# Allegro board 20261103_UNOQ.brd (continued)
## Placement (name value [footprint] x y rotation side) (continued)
NOREF#421  -  []  31.09 37.5 90 top
NOREF#422  -  []  26.18 34.44 90 top
NOREF#423  -  []  37.33 23.09 0 top
NOREF#424  -  []  32.63 31.65 0 top
NOREF#425  -  []  29.98 33.33 0 top
NOREF#426  -  []  11.96 5.57 0 top
NOREF#427  -  []  45.29 17.84 90 top
NOREF#428  -  []  38.04 5.75 90 top
NOREF#429  -  []  30.29 30.35 0 top
NOREF#430  -  []  25.17 14.33 90 top
NOREF#431  -  []  27.21 32.29 90 top
NOREF#432  -  []  39.59 23.12 0 top
NOREF#433  -  []  44.99 18.44 0 top
NOREF#434  -  []  6.83 30.58 0 top
NOREF#435  -  []  34.16 18.53 0 top
NOREF#436  -  []  38.35 10.47 90 top
NOREF#437  -  []  39.39 14.38 90 top
NOREF#438  -  []  51.05 59.19 0 top
NOREF#439  -  []  41.22 9.92 90 top
NOREF#440  -  []  4.79 58.74 0 top
NOREF#441  -  []  5.44 49.74 0 top
NOREF#442  -  [unnamed#2]  44.5 66.45 0 top
NOREF#443  -  []  34.13 49.99 0 top
NOREF#444  -  []  29.47 31.59 0 top
NOREF#445  -  []  33.69 37.47 90 top
NOREF#446  -  []  41.26 22.12 0 top
NOREF#447  -  []  22.48 4.07 90 top
NOREF#448  -  []  41.81 20.07 0 top
NOREF#449  -  []  37.38 20.26 0 top
NOREF#450  -  []  7.05 6.87 0 top
NOREF#451  -  []  34.08 34.26 90 top
NOREF#452  -  []  43.1 31.9 90 top
NOREF#453  -  []  22.61 16.36 90 top
NOREF#454  -  []  7.18 25.96 90 top
NOREF#455  -  []  16.45 23.37 0 top
NOREF#456  -  []  35.54 51.37 90 top
NOREF#457  -  []  30.81 29.87 90 top
NOREF#458  -  []  40.64 10.86 90 top
NOREF#459  -  []  36.64 51.25 0 top
NOREF#460  -  []  8.61 28.94 90 top
NOREF#461  -  []  33.21 30.88 0 top
NOREF#462  -  []  46.19 16.1 90 top
NOREF#463  -  []  7.42 30.66 0 top
NOREF#464  -  []  28.23 32.6 0 top
NOREF#465  -  []  31.5 29.7 0 top
NOREF#466  -  []  34.01 9.61 90 top
NOREF#467  -  []  14.91 52.28 90 top
NOREF#468  -  []  31.71 34.63 0 top
NOREF#469  -  []  28.69 12.65 90 top
NOREF#470  -  []  37.3 10.44 90 top
NOREF#471  -  []  26.86 31.75 90 top
NOREF#472  -  []  23.52 13.83 90 top
NOREF#473  -  []  35.32 55.63 0 top
NOREF#474  -  []  33.53 61.86 0 top
NOREF#475  -  []  21.25 3.91 0 top
NOREF#476  -  []  8.06 50.09 90 top
NOREF#477  -  []  9.5 38.04 90 top
NOREF#478  -  []  28.64 34.69 0 top
NOREF#479  -  []  50.8 22.86 90 top
NOREF#480  -  []  43.57 4.06 0 top
NOREF#481  -  []  21.53 14.32 0 top
NOREF#482  -  []  43.21 13.46 90 top
NOREF#483  -  []  41.45 32 0 top
NOREF#484  -  []  43.21 21.14 90 top
NOREF#485  -  []  33.31 34.78 0 top
NOREF#486  -  []  29.04 34.07 0 top
NOREF#487  -  []  13.14 34.87 90 top
NOREF#488  -  []  39.4 10.49 90 top
NOREF#489  -  []  12.45 0.62 90 top
NOREF#490  -  []  9.11 18.79 0 top
NOREF#491  -  []  40.45 33.9 0 top
NOREF#492  -  []  28.13 19.88 0 top
NOREF#493  -  []  30.46 37.19 90 top
NOREF#494  -  []  41.87 62.36 0 top
NOREF#495  -  []  33.1 31.5 0 top
NOREF#496  -  []  30.76 64.3 0 top
NOREF#497  -  []  28.33 63.1 90 top
NOREF#498  -  []  42.31 58.24 0 top
NOREF#499  -  []  36.7 52.56 90 top
NOREF#500  -  []  4.5 60.95 0 top
NOREF#501  -  []  23.52 13.83 0 top
NOREF#502  -  []  33.34 44.07 0 top
NOREF#503  -  []  29.65 29.62 0 top
NOREF#504  -  []  45.77 18.19 0 top
NOREF#505  -  []  29.05 35.73 90 top
NOREF#506  -  []  34.78 58.56 0 top
NOREF#507  -  []  6.21 49.48 0 top
NOREF#508  -  []  42.63 15.87 0 top
NOREF#509  -  []  29.7 33.01 90 top
NOREF#510  -  []  41.81 10.61 0 top
NOREF#511  -  []  28.91 63.42 90 top
NOREF#512  -  [unnamed#2]  50.8 53.34 0 top
NOREF#513  -  []  7.77 26.77 0 top
NOREF#514  -  []  29.85 17.44 0 top
NOREF#515  -  []  43.44 18.19 0 top
NOREF#516  -  []  30.5 38.22 0 top
NOREF#517  -  []  14.76 28.44 90 top
NOREF#518  -  []  6.37 57.11 0 top
NOREF#519  -  []  37.81 11.06 0 top
NOREF#520  -  []  6.47 25.38 0 top
NOREF#521  -  []  30.67 62.44 90 top
NOREF#522  -  []  37.06 49.13 90 top
NOREF#523  -  []  7.65 19.81 0 top
NOREF#524  -  []  30.01 30.78 90 top
NOREF#525  -  []  30.81 30.47 0 top
NOREF#526  -  []  33.22 53.5 90 top
NOREF#527  -  []  33.32 35.31 0 top
NOREF#528  -  []  43.77 16.91 0 top
NOREF#529  -  []  44.22 15.71 90 top
NOREF#530  -  []  38.72 27.21 90 top
NOREF#531  -  []  16.85 14.12 0 top
NOREF#532  -  []  43.72 4.91 0 top
NOREF#533  -  []  31.05 30.77 90 top
NOREF#534  -  []  26.11 13.85 90 top
NOREF#535  -  []  44.73 30.54 0 top
NOREF#536  -  []  44.53 45.74 90 top
NOREF#537  -  []  29.36 30.93 90 top
NOREF#538  -  []  13.92 20.21 0 top
NOREF#539  -  []  48.83 4.06 90 top
NOREF#540  -  []  39.4 12.15 0 top
NOREF#541  -  []  35.42 13.84 0 top
NOREF#542  -  []  31.55 36.55 0 top
NOREF#543  -  []  22.69 39.25 0 top
NOREF#544  -  []  29.37 36.58 0 top
NOREF#545  -  []  40.31 8.78 90 top
NOREF#546  -  []  16.38 49.79 90 top
NOREF#547  -  []  7.6 54.01 0 top
NOREF#548  -  []  9.19 19.77 90 top
NOREF#549  -  []  10.25 60.8 0 top
NOREF#550  -  []  29.05 37.29 90 top
NOREF#551  -  []  44.64 58.5 90 top
NOREF#552  -  []  25.55 61.39 0 top
NOREF#553  -  []  18.82 32.36 0 top
NOREF#554  -  []  25.91 35.59 0 top
NOREF#555  -  []  22.72 24.8 90 top
NOREF#556  -  []  21 13.82 90 top
NOREF#557  -  []  33.58 19.76 0 top
NOREF#558  -  []  12.09 39.74 90 top
NOREF#559  -  []  25.14 33.68 0 top
NOREF#560  -  []  22.6 4.75 90 top
NOREF#561  -  []  14.3 6.28 90 top
NOREF#562  -  []  29.46 64.99 90 top
NOREF#563  -  []  32.07 35.37 90 top
NOREF#564  -  []  31.07 32.41 90 top
NOREF#565  -  []  9.19 20.37 0 top
NOREF#566  -  []  12.09 31.7 0 top
NOREF#567  -  []  40.64 11.38 90 top
NOREF#568  -  []  27.86 29.22 0 top
NOREF#569  -  []  22.36 5.02 90 top
NOREF#570  -  []  15.78 49.79 0 top
NOREF#571  -  []  20.22 6.33 0 top
NOREF#572  -  []  31.19 16.1 0 top
NOREF#573  -  []  13.02 53.22 90 top
NOREF#574  -  []  42.85 58.66 90 top
NOREF#575  -  []  27.3 13.38 90 top
NOREF#576  -  []  38.62 59.48 0 top
NOREF#577  -  []  33.42 29.65 90 top
NOREF#578  -  []  37 46.32 90 top
NOREF#579  -  []  30.74 33.85 90 top
NOREF#580  -  []  34.25 24.2 90 top
NOREF#581  -  []  22.25 28.65 0 top
NOREF#582  -  []  15.57 14.13 0 top
NOREF#583  -  []  23.47 55.71 90 top
NOREF#584  -  []  43.3 62.26 0 top
NOREF#585  -  []  11.38 50.09 90 top
NOREF#586  -  []  32.38 36.21 90 top
NOREF#587  -  []  25.91 36.13 0 top
NOREF#588  -  []  4.79 44.83 0 top
NOREF#589  -  []  38.28 22.04 0 top
NOREF#590  -  []  32.03 31.65 90 top
NOREF#591  -  []  7.16 19.18 90 top
NOREF#592  -  []  34.1 33.7 90 top
NOREF#593  -  []  17.56 45.35 90 top
NOREF#594  -  []  39.4 11.55 90 top
NOREF#595  -  []  39.75 32.83 0 top
NOREF#596  -  []  12.05 59.96 0 top
NOREF#597  -  []  15.85 52.5 90 top
NOREF#598  -  []  7.02 6.4 90 top
NOREF#599  -  []  40 33.25 90 top
NOREF#600  -  []  32.79 29.83 90 top
NOREF#601  -  []  33.1 49.59 90 top
NOREF#602  -  []  43.18 28.15 0 top
NOREF#603  -  []  33.89 45.89 90 top
NOREF#604  -  []  37.38 56.28 90 top
NOREF#605  -  []  46.8 58.49 0 top
NOREF#606  -  []  17.34 41.32 90 top
NOREF#607  -  []  7.29 21.97 0 top
NOREF#608  -  []  15.95 25.93 90 top
NOREF#609  -  []  17.61 13.49 90 top
NOREF#610  -  []  28.45 36.24 0 top
NOREF#611  -  []  39.75 34.98 90 top
NOREF#612  -  []  22.61 15.8 90 top
NOREF#613  -  []  21.67 40.32 0 top
NOREF#614  -  []  34.42 61.21 90 top
NOREF#615  -  []  20.99 4.75 90 top
NOREF#616  -  []  14.19 7.13 0 top
NOREF#617  -  []  22.99 38.11 90 top
NOREF#618  -  []  40.55 39.2 0 top
NOREF#619  -  []  8.44 13.65 0 top
NOREF#620  -  []  32.39 14.3 90 top
NOREF#621  -  []  32.8 18.91 0 top
NOREF#622  -  []  6.38 43.29 90 top
NOREF#623  -  []  14.99 37.82 90 top
NOREF#624  -  []  46.31 5.84 0 top
NOREF#625  -  []  35.74 11.53 90 top
NOREF#626  -  []  35.45 26.85 0 top
NOREF#627  -  []  11.48 31.49 0 top
NOREF#628  -  []  33.66 32.42 90 top
NOREF#629  -  []  13.03 13.63 90 top
NOREF#630  -  []  27.01 29.28 0 top
NOREF#631  -  []  11.2 14.13 90 top
NOREF#632  -  []  28.66 62.62 0 top
NOREF#633  -  []  28.29 38.06 90 top
NOREF#634  -  []  36.25 9.99 0 top
NOREF#635  -  []  32.67 35.37 0 top
NOREF#636  -  []  14.96 31.45 0 top
NOREF#637  -  []  40.19 12.4 0 top
NOREF#638  -  []  35.77 40.48 90 top
NOREF#639  -  []  25.31 35.59 90 top
NOREF#640  -  []  17.05 23.97 90 top
NOREF#641  -  []  28.63 37.64 0 top
NOREF#642  -  []  36.8 56.29 90 top
NOREF#643  -  []  30.07 31.59 90 top
NOREF#644  -  []  24.72 38.48 90 top
NOREF#645  -  []  33.68 13.24 90 top
NOREF#646  -  []  42.17 59.02 0 top
NOREF#647  -  []  19.05 49.79 0 top
NOREF#648  -  []  12.17 36.63 90 top
NOREF#649  -  []  46.23 47.26 0 top
NOREF#650  -  []  9.18 33.48 90 top
NOREF#651  -  []  34.25 25.25 90 top
NOREF#652  -  []  37.84 17.12 90 top
NOREF#653  -  []  15.9 37.12 90 top
NOREF#654  -  []  10.21 19.77 90 top
NOREF#655  -  []  13.94 18.24 90 top
NOREF#656  -  []  45.24 58.5 0 top
NOREF#657  -  []  39.11 53.14 90 top
NOREF#658  -  []  11.61 16.59 90 top
NOREF#659  -  []  38.71 43.35 0 top
NOREF#660  -  []  28.86 62.38 90 top
NOREF#661  -  []  35.57 37.88 90 top
NOREF#662  -  []  47.5 66.64 0 top
NOREF#663  -  []  9.51 19.01 90 top
NOREF#664  -  []  10.74 19.77 90 top
NOREF#665  -  []  38.81 53.74 0 top
NOREF#666  -  []  43.49 42.74 90 top
NOREF#667  -  []  42.35 30.8 90 top
NOREF#668  -  []  13.28 53.24 90 top
NOREF#669  -  []  26.15 38.35 90 top
NOREF#670  -  []  23.02 57.58 0 top
NOREF#671  -  []  35.06 51.14 90 top
NOREF#672  -  []  36.8 55.69 0 top
NOREF#673  -  []  25.25 59.23 90 top
NOREF#674  -  []  42.62 42.74 90 top
NOREF#675  -  []  44.21 23.17 0 top
NOREF#676  -  []  7.5 27.91 90 top
NOREF#677  -  []  13.28 53.27 0 top
NOREF#678  -  []  14.3 14.13 0 top
NOREF#679  -  []  30.61 30.78 0 top
NOREF#680  -  []  14.45 59.96 0 top
NOREF#681  -  []  33 34.44 90 top
NOREF#682  -  []  19.33 6.62 0 top
NOREF#683  -  []  29.89 12.8 0 top
NOREF#684  -  []  32.63 36.81 0 top
NOREF#685  -  []  36.25 12.13 0 top
NOREF#686  -  []  31.2 35.75 90 top
NOREF#687  -  []  42.05 33.1 0 top
NOREF#688  -  []  42.63 16.39 0 top
NOREF#689  -  []  36.77 9.99 0 top
NOREF#690  -  []  7.72 30.06 90 top
NOREF#691  -  []  28.91 63.91 0 top
NOREF#692  -  []  26.87 32.97 90 top
NOREF#693  -  []  30.5 37.62 90 top
NOREF#694  -  []  37.72 57.46 90 top
NOREF#695  -  []  39.14 50.07 90 top
NOREF#696  -  []  11.85 13.52 0 top
NOREF#697  -  []  30.56 15.71 0 top
NOREF#698  -  []  7.13 24.67 90 top
NOREF#699  -  []  13.18 40.05 0 top
NOREF#700  -  []  46.36 32 0 top
NOREF#701  -  []  14.96 32.05 90 top
NOREF#702  -  []  43.4 48.14 0 top
NOREF#703  -  []  34.45 14.28 90 top
NOREF#704  -  []  36.7 43.04 90 top
NOREF#705  -  []  34.45 18.81 0 top
NOREF#706  -  []  17.85 31.66 0 top
NOREF#707  -  []  25.73 13.58 0 top
NOREF#708  -  []  31.47 61.95 90 top
NOREF#709  -  []  22.69 39.76 0 top
NOREF#710  -  []  31.34 33.85 0 top
NOREF#711  -  []  27.78 34.51 90 top
NOREF#712  -  []  32.19 30.85 0 top
NOREF#713  -  []  22.88 14.23 90 top
NOREF#714  -  []  38.12 27.51 0 top
NOREF#715  -  []  20.22 15.05 90 top
NOREF#716  -  []  9.18 35.08 0 top
NOREF#717  -  []  16.26 22.23 0 top
NOREF#718  -  []  32.77 10.29 90 top
NOREF#719  -  []  42.38 58.95 90 top
NOREF#720  -  []  30.67 18.33 90 top
NOREF#721  -  []  31.75 35.16 0 top
NOREF#722  -  []  24.49 13.62 90 top
NOREF#723  -  []  46.33 32.64 90 top
NOREF#724  -  []  14.99 37.22 0 top
NOREF#725  -  []  49.55 3.56 0 top
NOREF#726  -  []  40.04 11.38 0 top
NOREF#727  -  []  32.44 43.47 90 top
NOREF#728  -  []  8.12 38.81 0 top
NOREF#729  -  []  44.66 57.55 0 top
NOREF#730  -  []  43.21 14.06 0 top
NOREF#731  -  []  29.14 38.23 90 top
NOREF#732  -  []  43.5 24.23 0 top
NOREF#733  -  []  36.99 43.47 0 top
NOREF#734  -  []  40.43 5.34 90 top
NOREF#735  -  []  44.66 57.55 90 top
NOREF#736  -  []  22.2 13.59 90 top
NOREF#737  -  []  26.36 32.97 90 top
NOREF#738  -  []  8.5 43.1 0 top
NOREF#739  -  []  20.34 4.01 90 top
NOREF#740  -  []  32.39 13.28 90 top
NOREF#741  -  []  42.63 16.92 0 top
NOREF#742  -  []  39.11 52.63 90 top
NOREF#743  -  []  46.26 40.46 90 top
NOREF#744  -  []  31.77 50.66 90 top
NOREF#745  -  []  34.03 23.1 0 top
NOREF#746  -  []  1.06 49.93 0 top
NOREF#747  -  []  27.29 13.41 90 top
NOREF#748  -  []  30.62 22.07 90 top
NOREF#749  -  []  29.36 30.33 0 top
NOREF#750  -  []  36.78 10.44 90 top
NOREF#751  -  []  28.03 63.19 0 top
NOREF#752  -  []  15.98 27.43 90 top
NOREF#753  -  []  36.39 58.05 90 top
NOREF#754  -  []  39.4 43.42 0 top
NOREF#755  -  []  45.12 21.66 0 top
NOREF#756  -  []  10.9 31.85 90 top
NOREF#757  -  []  40 29.9 90 top
NOREF#758  -  []  37.71 39.22 0 top
NOREF#759  -  []  32.57 49.59 90 top
NOREF#760  -  []  13.36 16.12 0 top
NOREF#761  -  []  45.02 4.06 90 top
NOREF#762  -  []  42.17 61.86 90 top
NOREF#763  -  []  32.64 32.67 0 top
NOREF#764  -  []  46.17 12.58 0 top
NOREF#765  -  []  21.97 38.65 90 top
NOREF#766  -  []  29.05 36.24 90 top
NOREF#767  -  []  15.22 42.62 0 top
NOREF#768  -  []  7.6 52.87 90 top
NOREF#769  -  []  14.65 53.7 0 top
NOREF#770  -  []  43.62 4.01 0 top
NOREF#771  -  []  16.22 36.1 90 top
NOREF#772  -  []  30.12 19.23 90 top
NOREF#773  -  []  15.45 49.58 90 top
NOREF#774  -  []  44.17 4.91 0 top
NOREF#775  -  []  38.22 21.23 90 top
NOREF#776  -  []  21.16 6.29 90 top
NOREF#777  -  []  30.6 35.75 0 top
NOREF#778  -  []  47.38 4.06 0 top
NOREF#779  -  []  17.85 33.87 0 top
NOREF#780  -  []  20.86 15.24 0 top
NOREF#781  -  []  36.76 49.73 0 top
NOREF#782  -  []  22.85 28.65 0 top
NOREF#783  -  []  31.53 38.71 90 top
NOREF#784  -  []  27.85 30.1 0 top
NOREF#785  -  []  32.79 9.55 90 top
NOREF#786  -  []  14.14 52.54 90 top
NOREF#787  -  []  44.59 42.55 90 top
NOREF#788  -  []  43.05 42.77 90 top
NOREF#789  -  []  15.97 20.4 0 top
NOREF#790  -  []  36.45 13.84 0 top
NOREF#791  -  []  18.58 36.25 90 top
NOREF#792  -  []  12.79 53.02 90 top
NOREF#793  -  []  7.87 21.37 90 top
NOREF#794  -  []  29.1 19.23 90 top
NOREF#795  -  []  26.77 36.61 0 top
NOREF#796  -  []  26.2 31.04 0 top
NOREF#797  -  []  35.08 57.97 90 top
NOREF#798  -  []  29.12 30.86 0 top
NOREF#799  -  []  46.47 3.06 90 top
NOREF#800  -  []  45.47 4.06 0 top
NOREF#801  -  []  39.97 27.68 0 top
NOREF#802  -  []  17.17 13.5 90 top
NOREF#803  -  []  30.74 33.34 90 top
NOREF#804  -  []  14.64 32.39 90 top
NOREF#805  -  []  44.21 21.14 0 top
NOREF#806  -  []  7.1 4.77 0 top
NOREF#807  -  [unnamed#2]  2.54 54.61 0 top
NOREF#808  -  []  8.9 21.61 90 top
NOREF#809  -  []  39.1 34.95 90 top
NOREF#810  -  []  8.84 29.54 0 top
NOREF#811  -  []  34.97 61.23 0 top
NOREF#812  -  []  28.5 59.57 90 top
NOREF#813  -  []  34.54 34.83 90 top
NOREF#814  -  []  18.46 5.95 0 top
NOREF#815  -  []  28.87 63.91 0 top
NOREF#816  -  []  38.43 5.78 0 top
NOREF#817  -  []  25.73 34.57 0 top
NOREF#818  -  []  45.26 18.38 90 top
NOREF#819  -  []  28.45 35.73 0 top
NOREF#820  -  []  12.13 31.77 90 top
NOREF#821  -  []  35.7 52.45 0 top
NOREF#822  -  []  29.28 35.21 90 top
NOREF#823  -  []  24.85 58.48 90 top
NOREF#824  -  []  45.62 4.91 0 top
NOREF#825  -  []  17.73 64.55 0 top
NOREF#826  -  []  37.3 11.04 0 top
NOREF#827  -  []  30.99 37.19 90 top
NOREF#828  -  []  19.63 32.62 0 top
NOREF#829  -  []  6.96 37.6 90 top
NOREF#830  -  []  30.26 61.59 0 top
NOREF#831  -  []  11.85 14.12 90 top
NOREF#832  -  []  12.68 40.05 0 top
NOREF#833  -  []  13.03 14.13 0 top
NOREF#834  -  []  30.38 32 90 top
NOREF#835  -  []  29.14 33.01 90 top
NOREF#836  -  []  11.87 20.6 0 top
NOREF#837  -  []  45.62 45.85 90 top
NOREF#838  -  []  36.37 49.13 90 top
NOREF#839  -  []  29.19 63.29 90 top
NOREF#840  -  []  30.37 63.04 0 top
NOREF#841  -  []  28.45 57.12 0 top
NOREF#842  -  []  14.46 29.64 0 top
NOREF#843  -  []  35.86 49.13 90 top
NOREF#844  -  []  39 55.87 0 top
NOREF#845  -  []  44.38 42.74 90 top
NOREF#846  -  []  34.03 23.73 0 top
NOREF#847  -  []  15.57 13.63 90 top
NOREF#848  -  []  33.68 49.91 0 top
NOREF#849  -  []  35.14 15.92 0 top
NOREF#850  -  []  34.82 43.48 90 top
NOREF#851  -  []  37.17 38.26 90 top
NOREF#852  -  []  33.92 35.82 90 top
NOREF#853  -  []  29.7 32.41 0 top
NOREF#854  -  []  46.53 46.66 90 top
NOREF#855  -  []  28.36 15.6 90 top
NOREF#856  -  []  38.92 58.88 90 top
NOREF#857  -  []  2.54 17.78 90 top
NOREF#858  -  []  38.47 5.54 90 top
NOREF#859  -  []  34.63 23.1 90 top
NOREF#860  -  []  31.13 30.25 90 top
NOREF#861  -  []  13.51 13.89 90 top
NOREF#862  -  []  38.35 12.13 0 top
NOREF#863  -  []  40.55 31.4 0 top
NOREF#864  -  []  29.83 61.45 90 top
NOREF#865  -  []  38.35 11.53 90 top
NOREF#866  -  []  28.31 34.52 90 top
NOREF#867  -  []  45.32 47.52 0 top
NOREF#868  -  []  38.05 33.62 0 top
NOREF#869  -  []  16.05 38.12 90 top
NOREF#870  -  []  29.11 13.64 0 top
NOREF#871  -  []  38.28 23.04 90 top
NOREF#872  -  []  12.77 36.63 0 top
NOREF#873  -  []  21.23 3.28 0 top
NOREF#874  -  []  21.83 13.72 90 top
NOREF#875  -  []  38.86 6.26 0 top
NOREF#876  -  []  21.16 6.61 0 top
NOREF#877  -  []  27.12 33.5 0 top
NOREF#878  -  []  10.91 13.47 90 top
NOREF#879  -  []  32.47 9.99 0 top
NOREF#880  -  []  6.68 24.6 0 top
NOREF#881  -  []  27.4 36.27 0 top
NOREF#882  -  []  31.39 43.48 90 top
NOREF#883  -  []  16.72 22.08 90 top
NOREF#884  -  []  43.44 19.21 0 top
NOREF#885  -  []  6.96 38.2 0 top
NOREF#886  -  []  44.13 62.93 0 top
NOREF#887  -  []  41.28 4.84 90 top
NOREF#888  -  []  19.32 6.34 90 top
NOREF#889  -  []  38.35 31.9 90 top
NOREF#890  -  []  44.2 43.09 0 top
NOREF#891  -  []  27.48 13.35 90 top
NOREF#892  -  []  1.61 49.14 90 top
NOREF#893  -  []  35.56 49.73 0 top
NOREF#894  -  []  32.8 36.5 0 top
NOREF#895  -  []  32.99 15.82 0 top
NOREF#896  -  []  41.35 34.5 0 top
NOREF#897  -  []  36.25 9.39 90 top
NOREF#898  -  []  43.8 17.44 0 top
NOREF#899  -  []  25.85 57.03 90 top
NOREF#900  -  []  33 35.04 0 top
NOREF#901  -  []  17.56 45.53 90 top
NOREF#902  -  []  51.3 58.49 90 top
NOREF#903  -  []  28.96 65.99 0 top
NOREF#904  -  [unnamed#2]  7.62 2.54 0 top
NOREF#905  -  []  29.1 20.23 0 top
NOREF#906  -  []  41.65 33.9 90 top
NOREF#907  -  []  8.63 19.77 90 top
NOREF#908  -  []  20.97 4.79 90 top
NOREF#909  -  []  46.86 27.03 90 top
NOREF#910  -  []  43.48 62.66 0 top
NOREF#911  -  []  18.54 31.89 90 top
NOREF#912  -  []  6.37 58.11 90 top
NOREF#913  -  []  37.9 35.25 0 top
NOREF#914  -  []  24.43 16.2 0 top
NOREF#915  -  []  30.62 21.07 0 top
NOREF#916  -  []  34.18 19.76 90 top
NOREF#917  -  []  21.28 4.52 0 top
NOREF#918  -  []  32.36 53.54 0 top
NOREF#919  -  []  33.17 37.76 90 top
NOREF#920  -  []  1.61 50.28 0 top
NOREF#921  -  []  37.33 24.09 90 top
NOREF#922  -  []  16.05 13.89 90 top
NOREF#923  -  []  41.05 40.81 90 top
NOREF#924  -  []  12.98 39.45 90 top
NOREF#925  -  []  11.52 43.17 0 top
NOREF#926  -  []  30.3 62.3 0 top
NOREF#927  -  []  14.95 53.1 90 top
NOREF#928  -  []  14.11 16.12 0 top
NOREF#929  -  []  29.22 24.8 0 top
NOREF#930  -  []  30.32 35.23 90 top
NOREF#931  -  []  43.68 47.52 90 top
NOREF#932  -  []  20.99 4.79 0 top
NOREF#933  -  []  21.53 2.68 90 top
NOREF#934  -  []  38.43 5.16 90 top
NOREF#935  -  []  35.97 28.28 90 top
NOREF#936  -  []  28.86 17.44 0 top
NOREF#937  -  []  3.43 61.47 90 top
NOREF#938  -  []  38.81 54.35 0 top
NOREF#939  -  []  26.34 13.58 90 top
NOREF#940  -  []  29.47 32.1 0 top
NOREF#941  -  []  6.86 19.78 0 top
NOREF#942  -  []  43.57 62.81 90 top
NOREF#943  -  []  44.84 57.52 90 top
NOREF#944  -  []  10.94 35.55 0 top
NOREF#945  -  []  32.99 15.31 0 top
NOREF#946  -  []  31.69 37.5 0 top
NOREF#947  -  []  26.53 35.59 90 top
NOREF#948  -  []  23.42 14.23 90 top
NOREF#949  -  []  15.3 28.44 90 top
NOREF#950  -  []  15.3 19.8 90 top
NOREF#951  -  []  44.1 61.65 90 top
NOREF#952  -  []  38.8 51.88 0 top
NOREF#953  -  []  30.94 26.12 90 top
NOREF#954  -  []  43.07 59.24 0 top
NOREF#955  -  []  6.75 6.41 90 top
NOREF#956  -  []  26.23 36.61 0 top
NOREF#957  -  []  27.81 33.68 0 top
NOREF#958  -  []  16.53 24.36 90 top
NOREF#959  -  []  34.5 34.51 0 top
NOREF#960  -  []  32.66 31.42 90 top
NOREF#961  -  []  26.88 15.29 0 top
NOREF#962  -  []  42.95 32.67 0 top
NOREF#963  -  []  17.85 31.29 90 top
NOREF#964  -  []  39.11 53.75 90 top
NOREF#965  -  []  31.09 44.08 0 top
NOREF#966  -  []  46.33 33.24 0 top
NOREF#967  -  []  28.31 35.12 0 top
NOREF#968  -  []  11.54 33.15 90 top
NOREF#969  -  []  29.05 59.57 90 top
NOREF#970  -  []  12.85 5.1 0 top
NOREF#971  -  []  34.52 44.08 0 top
NOREF#972  -  []  31.34 33.34 0 top
NOREF#973  -  []  28.01 35.75 90 top
NOREF#974  -  []  39.14 50.61 90 top
NOREF#975  -  []  38.87 12.13 0 top
NOREF#976  -  []  44.35 43.05 0 top
NOREF#977  -  []  42.05 32.98 0 top
NOREF#978  -  []  34.7 13.24 90 top
NOREF#979  -  []  20.1 5.05 0 top
NOREF#980  -  []  17.63 25.22 0 top
NOREF#981  -  []  21.67 39.76 0 top
NOREF#982  -  []  3.93 60.64 90 top
NOREF#983  -  []  31.18 26.72 0 top
NOREF#984  -  []  30.53 33.01 0 top
NOREF#985  -  []  38.47 5.28 90 top
NOREF#986  -  []  33.06 32.96 0 top
NOREF#987  -  []  33.69 12.8 90 top
NOREF#988  -  []  39.25 31.3 90 top
NOREF#989  -  []  7.62 20.01 90 top
NOREF#990  -  []  13.71 6.73 0 top
NOREF#991  -  []  35.37 52.86 0 top
NOREF#992  -  []  12.08 30.89 90 top
NOREF#993  -  []  35.78 9.66 90 top
NOREF#994  -  []  24.51 13.62 0 top
NOREF#995  -  []  8.67 13.38 90 top
NOREF#996  -  []  33.42 30.25 0 top
NOREF#997  -  []  33.4 36.5 90 top
NOREF#998  -  []  38.16 52.52 90 top
NOREF#999  -  []  27.39 30.13 0 top
NOREF#1000  -  []  17.73 22.18 90 top
NOREF#1001  -  []  29.14 32.41 0 top
NOREF#1002  -  []  15.55 6.6 0 top
NOREF#1003  -  []  14.9 47.39 90 top
NOREF#1004  -  []  33.86 57.05 90 top
NOREF#1005  -  []  19.05 34.35 90 top
NOREF#1006  -  []  30.49 4.91 90 top
NOREF#1007  -  []  32.63 37.41 90 top
NOREF#1008  -  []  11.61 15.59 90 top
NOREF#1009  -  []  35.52 40.92 90 top
NOREF#1010  -  []  27.03 60.98 90 top
NOREF#1011  -  []  39.11 51.92 90 top
NOREF#1012  -  []  28.41 33.68 90 top
NOREF#1013  -  []  33.39 46.89 0 top
NOREF#1014  -  []  41.28 20.07 0 top
NOREF#1015  -  []  42.35 32.5 90 top
NOREF#1016  -  []  40.25 26.68 90 top
NOREF#1017  -  []  40.25 62.67 0 top
NOREF#1018  -  []  14.45 43.6 90 top
NOREF#1019  -  []  1.02 41.89 0 top
NOREF#1020  -  []  34 30.01 0 top
NOREF#1021  -  []  15.88 47.18 0 top
NOREF#1022  -  []  31.99 26.12 90 top
NOREF#1023  -  []  37.84 16.12 90 top
NOREF#1024  -  []  43.35 28.68 90 top
NOREF#1025  -  []  46.12 20.64 90 top
NOREF#1026  -  []  45.52 4.01 0 top
NOREF#1027  -  []  8.07 14.25 0 top
NOREF#1028  -  []  18.46 5.95 90 top
NOREF#1029  -  []  25.85 60.79 90 top
NOREF#1030  -  []  14.37 46.28 90 top
NOREF#1031  -  []  11.52 43.17 0 top
NOREF#1032  -  []  38.87 11.53 90 top
NOREF#1033  -  []  38.29 18.26 90 top
NOREF#1034  -  []  15.95 25.33 0 top
NOREF#1035  -  []  22.58 14.83 0 top
NOREF#1036  -  []  20.1 4.76 0 top
NOREF#1037  -  []  27.08 36.19 0 top
NOREF#1038  -  []  33.69 19.45 0 top
NOREF#1039  -  []  37.05 53.11 0 top
NOREF#1040  -  []  40.67 18.81 0 top
NOREF#1041  -  []  33.16 33.28 90 top
NOREF#1042  -  []  26.01 29.28 90 top
NOREF#1043  -  []  9.72 49.79 90 top
NOREF#1044  -  []  43.8 23.63 90 top
NOREF#1045  -  []  16.23 24.96 0 top
NOREF#1046  -  []  32.39 13.79 90 top
NOREF#1047  -  []  47.01 57.27 0 top
NOREF#1048  -  []  32.06 37.57 0 top
NOREF#1049  -  []  28 36.27 90 top
NOREF#1050  -  []  21.67 38.14 0 top
NOREF#1051  -  []  13.64 18.84 0 top
NOREF#1052  -  []  5.74 49.14 90 top
NOREF#1053  -  []  42.66 3.06 90 top
NOREF#1054  -  []  45.55 33.1 90 top
NOREF#1055  -  []  15.52 42.02 90 top
NOREF#1056  -  []  39.36 5.26 90 top
NOREF#1057  -  []  11.98 50.09 0 top
NOREF#1058  -  []  29.12 30.26 90 top
NOREF#1059  -  []  34.13 11.33 90 top
NOREF#1060  -  []  6.77 24.78 90 top
NOREF#1061  -  []  29.89 13.35 0 top
NOREF#1062  -  []  34.18 20.39 90 top
NOREF#1063  -  []  41.28 20.67 90 top
NOREF#1064  -  []  36.29 23.09 0 top
NOREF#1065  -  []  46.81 4.84 90 top
NOREF#1066  -  []  15.74 47.59 90 top
NOREF#1067  -  []  37.24 17.12 0 top
NOREF#1068  -  []  36.25 11.53 90 top
NOREF#1069  -  []  13.03 49.79 90 top
NOREF#1070  -  []  4.23 62.9 0 top
NOREF#1071  -  []  28.91 13.34 90 top
NOREF#1072  -  []  40.04 10.86 0 top
NOREF#1073  -  []  22.31 16.4 0 top
NOREF#1074  -  []  40.47 37.51 90 top
NOREF#1075  -  []  30.51 35.97 90 top
NOREF#1076  -  []  40.68 20.29 0 top
NOREF#1077  -  []  38.78 10.04 0 top
NOREF#1078  -  []  24.73 15.6 90 top
NOREF#1079  -  []  46.07 4.91 0 top
NOREF#1080  -  []  39.85 30.68 90 top
NOREF#1081  -  []  39.85 30.68 0 top
NOREF#1082  -  []  4.8 60.35 90 top
NOREF#1083  -  []  6.96 29.05 0 top
NOREF#1084  -  []  27.48 14.76 90 top
NOREF#1085  -  []  15.86 7.11 0 top
NOREF#1086  -  []  9.56 46.43 0 top
NOREF#1087  -  []  37.29 49.73 0 top
NOREF#1088  -  []  39.08 9.44 90 top
NOREF#1089  -  []  16.92 36.25 90 top
NOREF#1090  -  []  40.41 31.53 90 top
NOREF#1091  -  []  19.93 32.02 90 top
NOREF#1092  -  []  10.56 45.83 90 top
NOREF#1093  -  []  35.85 58.05 90 top
NOREF#1094  -  []  28.8 52.13 90 top
NOREF#1095  -  []  32.66 54.03 0 top
NOREF#1096  -  []  25.16 32.34 90 top
NOREF#1097  -  []  47.24 56.79 90 top
NOREF#1098  -  []  19.23 63.73 0 top
NOREF#1099  -  []  15.46 46.35 0 top
NOREF#1100  -  []  6.98 24 90 top
NOREF#1101  -  []  8.63 20.37 0 top
NOREF#1102  -  []  21.97 37.54 90 top
NOREF#1103  -  []  16.92 36.55 0 top
NOREF#1104  -  []  11.61 15.59 90 top
NOREF#1105  -  []  44.38 16.91 90 top
NOREF#1106  -  []  44.6 33.25 0 top
NOREF#1107  -  []  34.18 21.03 90 top
NOREF#1108  -  []  15.86 13.51 90 top
NOREF#1109  -  []  43.94 45.06 0 top
NOREF#1110  -  []  23.58 62.85 0 top
NOREF#1111  -  []  14.6 19.28 90 top
NOREF#1112  -  []  44.47 5.84 0 top
NOREF#1113  -  []  39.95 3.93 90 top
NOREF#1114  -  []  36.22 15.58 0 top
NOREF#1115  -  []  32.92 54.1 0 top
NOREF#1116  -  []  34.62 22.5 0 top
NOREF#1117  -  []  44.1 12.61 90 top
NOREF#1118  -  []  43.92 16.31 0 top
NOREF#1119  -  []  35.22 42.03 0 top
NOREF#1120  -  []  47.43 4.01 0 top
NOREF#1121  -  []  20.8 13.52 90 top
NOREF#1122  -  []  29.93 36.59 0 top
NOREF#1123  -  []  46.92 3.61 90 top
NOREF#1124  -  []  42.43 43.09 0 top
NOREF#1125  -  []  37.65 52.51 90 top
NOREF#1126  -  []  29.05 36.78 90 top
NOREF#1127  -  []  22.89 53.15 90 top
NOREF#1128  -  []  32.38 34.11 90 top
NOREF#1129  -  []  43.71 44.63 0 top
NOREF#1130  -  []  44.4 60.56 90 top
NOREF#1131  -  []  31.48 26.12 90 top
NOREF#1132  -  []  31.5 29.1 90 top
NOREF#1133  -  []  34.2 20.53 90 top
NOREF#1134  -  []  34.13 11.93 0 top
NOREF#1135  -  []  30.38 31.4 0 top
NOREF#1136  -  []  22.72 24.3 90 top
NOREF#1137  -  []  33.53 66.41 0 top
NOREF#1138  -  []  37.81 12.13 0 top
NOREF#1139  -  []  32.14 44.07 0 top
NOREF#1140  -  []  43.23 16.39 90 top
NOREF#1141  -  []  21.58 3.92 90 top
NOREF#1142  -  []  40.57 27.68 90 top
NOREF#1143  -  []  32.2 18.91 90 top
NOREF#1144  -  []  41.02 11.02 90 top
NOREF#1145  -  []  29.6 21.07 0 top
NOREF#1146  -  []  26.79 30.13 90 top
NOREF#1147  -  []  38.27 10.05 0 top
NOREF#1148  -  []  24.17 75.31 0 top
NOREF#1149  -  []  12.97 6.31 90 top
NOREF#1150  -  []  12.17 36.04 90 top
NOREF#1151  -  []  24.83 31.36 90 top
NOREF#1152  -  []  12.05 58.76 90 top
NOREF#1153  -  []  39.3 50.88 90 top
NOREF#1154  -  []  29.22 6.18 0 top
NOREF#1155  -  []  4.53 63.04 90 top
NOREF#1156  -  []  25.91 13.55 90 top
NOREF#1157  -  []  7.29 21.37 90 top
NOREF#1158  -  []  30.49 7.45 0 top
NOREF#1159  -  []  15.05 43.9 0 top
NOREF#1160  -  []  35.2 21.48 0 top
NOREF#1161  -  []  51.3 59.19 0 top
NOREF#1162  -  []  21.64 6.33 90 top
NOREF#1163  -  []  42.66 42.25 0 top
NOREF#1164  -  []  35.06 50.63 90 top
NOREF#1165  -  []  14.64 33.34 90 top
NOREF#1166  -  []  35.71 8.37 90 top
NOREF#1167  -  []  7.02 6.4 0 top
NOREF#1168  -  []  35.67 52.86 90 top
NOREF#1169  -  []  7.05 53.66 0 top
NOREF#1170  -  []  7.86 57.13 0 top
NOREF#1171  -  []  38.88 11.09 0 top
NOREF#1172  -  []  25.3 15.6 90 top
NOREF#1173  -  []  24.72 74.04 90 top
NOREF#1174  -  []  12.98 6.31 0 top
NOREF#1175  -  []  46.53 46.11 90 top
NOREF#1176  -  []  25.47 31.36 90 top
NOREF#1177  -  []  46.34 44.01 0 top
NOREF#1178  -  []  32.65 19.68 0 top
NOREF#1179  -  []  36.55 10.44 90 top
NOREF#1180  -  []  16.17 41.24 0 top
NOREF#1181  -  []  40.68 22.29 90 top
NOREF#1182  -  []  3.63 61.24 0 top
NOREF#1183  -  []  26.53 36.19 0 top
NOREF#1184  -  []  22.99 37.54 90 top
NOREF#1185  -  []  17.84 5.96 90 top
NOREF#1186  -  []  36.39 57.45 0 top
NOREF#1187  -  []  17.55 5.97 90 top
NOREF#1188  -  []  19.33 6.3 90 top
NOREF#1189  -  []  22.89 53.75 0 top
NOREF#1190  -  []  35.52 41.43 90 top
NOREF#1191  -  []  30.6 61.7 90 top
NOREF#1192  -  []  43.7 42.55 90 top
NOREF#1193  -  []  37.56 53.12 0 top
NOREF#1194  -  []  35.74 11.04 0 top
NOREF#1195  -  []  20.22 6.62 0 top
NOREF#1196  -  []  30.07 32.1 90 top
NOREF#1197  -  []  26.2 32.29 90 top
NOREF#1198  -  []  31.79 14.05 90 top
NOREF#1199  -  []  10.34 35.24 0 top
NOREF#1200  -  []  32.19 29.83 0 top
NOREF#1201  -  []  5.43 57.11 0 top
NOREF#1202  -  []  38.47 5.78 0 top
NOREF#1203  -  []  21.67 37.57 0 top
NOREF#1204  -  []  37.54 6.75 0 top
NOREF#1205  -  []  36.29 24.09 90 top
NOREF#1206  -  []  34.95 49.56 90 top
NOREF#1207  -  []  8.44 63.73 90 top
NOREF#1208  -  []  9.5 36.14 90 top
NOREF#1209  -  []  40.75 34.5 90 top
NOREF#1210  -  []  21.97 36.97 90 top
NOREF#1211  -  []  17.43 22.78 0 top
NOREF#1212  -  []  15 29.64 0 top
NOREF#1213  -  []  37.64 43.34 0 top
NOREF#1214  -  []  34.57 51.14 0 top
NOREF#1215  -  []  43.16 62.9 0 top
NOREF#1216  -  []  39.11 51.39 90 top
NOREF#1217  -  []  13.6 50.29 0 top
NOREF#1218  -  []  39.09 14.23 90 top
NOREF#1219  -  []  44.96 18.98 0 top
NOREF#1220  -  []  33.81 30.88 90 top
NOREF#1221  -  []  30.75 61.3 90 top
NOREF#1222  -  []  43.55 5.84 0 top
NOREF#1223  -  []  25.85 59.93 0 top
NOREF#1224  -  []  32.67 18.33 0 top
NOREF#1225  -  []  4.23 63.64 0 top
NOREF#1226  -  []  25.17 76.15 0 top
NOREF#1227  -  []  42.81 42.55 90 top
NOREF#1228  -  []  10.01 18.79 0 top
NOREF#1229  -  []  42.58 43.05 0 top
NOREF#1230  -  []  33.48 34.26 0 top
NOREF#1231  -  []  34.8 11.33 0 top
NOREF#1232  -  []  32.63 32.16 0 top
NOREF#1233  -  []  22.18 4.67 0 top
NOREF#1234  -  []  20.99 5.07 0 top
NOREF#1235  -  []  28.36 16.6 0 top
NOREF#1236  -  []  38.16 43.34 0 top
NOREF#1237  -  []  49 58.49 90 top
NOREF#1238  -  []  30.53 32.41 90 top
NOREF#1239  -  []  15.73 6.25 90 top
NOREF#1240  -  []  7.73 24.67 0 top
NOREF#1241  -  []  36.82 15.58 90 top
NOREF#1242  -  []  9.12 49.79 0 top
NOREF#1243  -  []  7.77 26.16 90 top
NOREF#1244  -  []  13.28 53.56 0 top
NOREF#1245  -  []  15.98 26.83 0 top
NOREF#1246  -  []  4.53 62.3 90 top
NOREF#1247  -  []  28.83 33.13 90 top
NOREF#1248  -  []  31.39 61.25 90 top
NOREF#1249  -  []  35.88 55.64 0 top
NOREF#1250  -  []  28.45 56.52 90 top
NOREF#1251  -  []  7.05 35.89 90 top
NOREF#1252  -  []  8.4 28.11 0 top
NOREF#1253  -  []  20.04 4.61 0 top
NOREF#1254  -  []  23.97 39.88 0 top
NOREF#1255  -  []  10.56 43.93 90 top
NOREF#1256  -  []  41.7 5.84 0 top
NOREF#1257  -  []  34.16 13.43 90 top
NOREF#1258  -  []  29.9 13.86 0 top
NOREF#1259  -  []  26.2 31.64 90 top
NOREF#1260  -  []  24.83 31.96 0 top
NOREF#1261  -  []  35.72 13.24 90 top
NOREF#1262  -  []  22.4 13.52 90 top
NOREF#1263  -  []  33.06 32.42 0 top
NOREF#1264  -  []  42.89 59.48 0 top
NOREF#1265  -  []  31.82 33.61 0 top
NOREF#1266  -  []  3.79 0.96 90 top
NOREF#1267  -  []  26.67 37.65 90 top
NOREF#1268  -  []  43.4 47.64 90 top
NOREF#1269  -  []  16.16 6.51 90 top
NOREF#1270  -  []  18.58 36.85 0 top
NOREF#1271  -  []  25.14 34.03 90 top
NOREF#1272  -  []  33.16 33.88 0 top
NOREF#1273  -  []  31.34 34.89 0 top
NOREF#1274  -  []  33.58 20.39 0 top
NOREF#1275  -  []  21.17 4.72 90 top
NOREF#1276  -  []  15.55 6.31 0 top
NOREF#1277  -  []  7.1 4.77 0 top
NOREF#1278  -  []  44.55 47.36 90 top
NOREF#1279  -  []  28.36 33.89 0 top
NOREF#1280  -  []  31.83 10.85 90 top
NOREF#1281  -  []  14.07 46.88 0 top
NOREF#1282  -  []  21.24 13.55 90 top
NOREF#1283  -  []  35.4 11.33 90 top
NOREF#1284  -  []  34.01 10.21 0 top
NOREF#1285  -  []  32.99 14.81 0 top
NOREF#1286  -  []  38.84 51.21 0 top
NOREF#1287  -  []  6.75 36.49 0 top
NOREF#1288  -  []  45.62 46.92 90 top
NOREF#1289  -  []  31 31.78 90 top
NOREF#1290  -  []  23.47 54.71 0 top
NOREF#1291  -  []  13.36 16.12 0 top
NOREF#1292  -  []  8.5 38.64 0 top
NOREF#1293  -  []  43.31 64.37 0 top
NOREF#1294  -  []  32.39 15.82 90 top
NOREF#1295  -  []  50.8 26.92 90 top
NOREF#1296  -  []  23.13 13.56 0 top
NOREF#1297  -  []  29.77 40.28 0 top
NOREF#1298  -  []  11.37 40.48 0 top
NOREF#1299  -  []  38.95 30.98 0 top
NOREF#1300  -  []  40.62 24.12 90 top
NOREF#1301  -  []  21.55 3.31 90 top
NOREF#1302  -  []  47.01 56.99 0 top
NOREF#1303  -  []  13.84 53.14 0 top
NOREF#1304  -  []  14.78 13.89 90 top
NOREF#1305  -  []  29.35 15.6 90 top
NOREF#1306  -  []  44.01 24.24 0 top
NOREF#1307  -  []  32.99 13.28 0 top
NOREF#1308  -  []  32.57 50.19 0 top
NOREF#1309  -  []  43.3 62.69 0 top
NOREF#1310  -  []  36.5 47.32 0 top
NOREF#1311  -  []  31.6 31.78 0 top
NOREF#1312  -  []  25.3 35.08 90 top
NOREF#1313  -  []  29.35 16.6 0 top
NOREF#1314  -  []  45.25 33.7 0 top
NOREF#1315  -  []  20.2 6.33 90 top
NOREF#1316  -  []  32.79 30.34 90 top
NOREF#1317  -  []  41.71 4.01 0 top
NOREF#1318  -  []  36.14 51.37 0 top
NOREF#1319  -  []  31.32 15.17 90 top
NOREF#1320  -  []  21 13.82 0 top
NOREF#1321  -  []  26.67 39.12 90 top
NOREF#1322  -  []  27.21 32.83 90 top
NOREF#1323  -  []  31.17 62.55 0 top
NOREF#1324  -  []  47.17 13.41 90 top
NOREF#1325  -  []  14.3 13.63 90 top
NOREF#1326  -  []  40.47 61.23 90 top
NOREF#1327  -  []  14.74 50.09 90 top
NOREF#1328  -  []  15.92 36.7 0 top
NOREF#1329  -  []  13.69 40.05 90 top
NOREF#1330  -  []  44.13 62.88 0 top
NOREF#1331  -  []  12.99 14.13 0 top
NOREF#1332  -  []  38.81 52.52 0 top
NOREF#1333  -  []  20.08 4.76 90 top
NOREF#1334  -  []  41.25 63.21 0 top
NOREF#1335  -  []  7.32 20.61 0 top
NOREF#1336  -  []  45.32 46.45 0 top
NOREF#1337  -  []  34.97 61.23 0 top
NOREF#1338  -  []  44.21 18.26 90 top
NOREF#1339  -  []  25.76 32.34 0 top
NOREF#1340  -  []  33.56 57.65 0 top
NOREF#1341  -  []  9.14 28.94 90 top
NOREF#1342  -  []  32.19 30.34 0 top
NOREF#1343  -  []  22.69 38.71 0 top
NOREF#1344  -  []  42.99 24.23 0 top
NOREF#1345  -  []  21.12 4.67 0 top
NOREF#1346  -  []  11.22 19.31 90 top
NOREF#1347  -  []  28.8 53.13 90 top
NOREF#1348  -  []  46.26 27.46 90 top
NOREF#1349  -  []  27.59 19.02 0 top
NOREF#1350  -  []  37.38 55.68 0 top
NOREF#1351  -  []  16.44 23.21 0 top
NOREF#1352  -  []  2.54 15.24 90 top
NOREF#1353  -  []  38.46 42.74 90 top
NOREF#1354  -  []  29.68 37.63 0 top
NOREF#1355  -  []  32.35 35.16 90 top
NOREF#1356  -  []  21.34 6.26 90 top
NOREF#1357  -  []  39.45 5.2 0 top
NOREF#1358  -  []  45.77 17.59 90 top
NOREF#1359  -  []  8.5 32.64 0 top
NOREF#1360  -  []  12.72 41.08 90 top
NOREF#1361  -  []  26.19 33.93 90 top
NOREF#1362  -  []  10.11 19.01 0 top
NOREF#1363  -  []  29.6 22.07 90 top
NOREF#1364  -  []  32.03 32.16 90 top
NOREF#1365  -  []  24.51 13.9 0 top
NOREF#1366  -  []  43.3 61.16 0 top
NOREF#1367  -  []  31.92 14.66 0 top
NOREF#1368  -  []  28.72 13.2 90 top
NOREF#1369  -  []  25.9 35.08 0 top
NOREF#1370  -  []  23.88 62.25 90 top
NOREF#1371  -  []  38.12 53.12 0 top
NOREF#1372  -  []  31.78 34.11 0 top
NOREF#1373  -  []  23.32 13.52 90 top
NOREF#1374  -  []  31.69 26.72 0 top
NOREF#1375  -  []  17.35 4.77 90 top
NOREF#1376  -  []  44.89 57.82 90 top
NOREF#1377  -  []  15.53 6.31 90 top
NOREF#1378  -  []  28.86 62.38 0 top
NOREF#1379  -  []  43.16 62.9 0 top
NOREF#1380  -  []  37.77 38.26 0 top
NOREF#1381  -  []  6.88 27.66 0 top
NOREF#1382  -  []  7.1 4.77 0 top
NOREF#1383  -  []  30.11 35.75 90 top
NOREF#1384  -  []  38.78 20.67 90 top
NOREF#1385  -  []  26.81 26.55 90 top
NOREF#1386  -  []  43.77 16.38 0 top
NOREF#1387  -  []  35.48 10.26 0 top
NOREF#1388  -  []  16.89 13.62 90 top
NOREF#1389  -  []  33.32 35.82 0 top
NOREF#1390  -  []  20.22 28.05 0 top
NOREF#1391  -  []  18.5 6.07 90 top
NOREF#1392  -  []  13.56 18.98 0 top
NOREF#1393  -  []  36.19 52.56 90 top
NOREF#1394  -  []  32.82 51.51 0 top
NOREF#1395  -  []  10.62 19.31 0 top
NOREF#1396  -  []  13.09 30.7 90 top
NOREF#1397  -  []  26.87 33.57 0 top
NOREF#1398  -  []  7.18 27.06 90 top
NOREF#1399  -  []  16.51 25.33 0 top
NOREF#1400  -  []  27.3 13.41 0 top
NOREF#1401  -  []  0.51 68.08 0 top
NOREF#1402  -  []  33.69 36.87 0 top
NOREF#1403  -  []  15.55 6.28 90 top
NOREF#1404  -  []  37.46 27.46 0 top
NOREF#1405  -  []  44.21 22.16 0 top
NOREF#1406  -  []  17.37 13.88 90 top
NOREF#1407  -  []  32.31 34.63 90 top
NOREF#1408  -  []  40.31 9.38 0 top
NOREF#1409  -  []  43.23 15.87 90 top
NOREF#1410  -  []  35.74 10.44 90 top
NOREF#1411  -  []  4.79 44.33 90 top
NOREF#1412  -  []  16.74 21.31 0 top
NOREF#1413  -  []  44.97 4.84 90 top
NOREF#1414  -  []  39.59 24.12 90 top
NOREF#1415  -  []  46.52 29.34 90 top
NOREF#1416  -  []  13.36 16.12 0 top
NOREF#1417  -  []  9.11 18.79 0 top
NOREF#1418  -  []  28.72 24.8 0 top
NOREF#1419  -  []  37.3 12.13 0 top
NOREF#1420  -  []  29.64 34.16 0 top
NOREF#1421  -  []  12.79 53.02 0 top
NOREF#1422  -  []  11.83 32.37 0 top
NOREF#1423  -  []  7.86 63.04 0 top
NOREF#1424  -  []  44.83 47.24 90 top
NOREF#1425  -  []  33.7 31.5 90 top
NOREF#1426  -  []  27.41 35.75 0 top
NOREF#1427  -  []  7.73 25.21 0 top
NOREF#1428  -  []  33.38 13.84 0 top
NOREF#1429  -  []  17.04 41.92 0 top
NOREF#1430  -  []  38.05 31.3 0 top
NOREF#1431  -  []  31.7 57.7 90 top
NOREF#1432  -  []  21.46 15.24 90 top
NOREF#1433  -  []  23.87 75.64 0 top
NOREF#1434  -  []  27.08 35.59 90 top
NOREF#1435  -  []  6.67 26.28 90 top
NOREF#1436  -  []  44.4 62.35 90 top
NOREF#1437  -  []  28.23 33.13 0 top
NOREF#1438  -  []  31.65 19.68 90 top
NOREF#1439  -  []  30.56 15.11 90 top
NOREF#1440  -  []  44.57 3.06 90 top
NOREF#1441  -  []  34.92 21.9 90 top
NOREF#1442  -  []  32.82 50.97 0 top
NOREF#1443  -  []  32.06 31.42 0 top
NOREF#1444  -  []  45.89 16.7 0 top
NOREF#1445  -  []  32.99 14.3 0 top
NOREF#1446  -  []  37.81 11.53 90 top
NOREF#1447  -  []  48.38 3.06 90 top
NOREF#1448  -  []  18.75 5.94 90 top
NOREF#1449  -  []  31.19 15.5 90 top
NOREF#1450  -  []  9.65 60.5 90 top
NOREF#1451  -  []  50.8 22.86 90 top
NOREF#1452  -  []  38.18 29.56 90 top
NOREF#1453  -  []  15.55 53.1 0 top
NOREF#1454  -  []  27.78 35.11 0 top
NOREF#1455  -  []  7.52 38.81 90 top
NOREF#1456  -  []  27.94 32.05 0 top
NOREF#1457  -  []  22.69 37.57 0 top
NOREF#1458  -  []  4.79 59.92 0 top
NOREF#1459  -  []  7.6 48.71 90 top
NOREF#1460  -  []  42.63 17.43 0 top
NOREF#1461  -  []  17.59 6.09 90 top
NOREF#1462  -  []  28.63 38.24 90 top
NOREF#1463  -  []  37.97 50.54 0 top
NOREF#1464  -  []  31.55 37.15 90 top
NOREF#1465  -  []  30.19 12.75 90 top
NOREF#1466  -  []  41.02 12.02 0 top
NOREF#1467  -  []  30.49 3.68 90 top
NOREF#1468  -  []  22.99 38.65 90 top
NOREF#1469  -  []  35.74 12.13 0 top
NOREF#1470  -  []  43.31 43.09 0 top
NOREF#1471  -  []  26.88 14.76 0 top
NOREF#1472  -  []  12.54 32.65 90 top
NOREF#1473  -  []  33.95 25.85 0 top
NOREF#1474  -  []  19.33 6.34 0 top
NOREF#1475  -  []  36 51.85 90 top
NOREF#1476  -  []  14.49 6.53 90 top
NOREF#1477  -  []  46.15 45.47 0 top
NOREF#1478  -  []  7.6 50.87 0 top
NOREF#1479  -  []  36.62 51.25 0 top
NOREF#1480  -  []  7.86 57.13 0 top
NOREF#1481  -  []  7.13 25.21 90 top
NOREF#1482  -  []  11.79 40.34 0 top
NOREF#1483  -  []  8.44 61.53 90 top
NOREF#1484  -  []  41.81 4.91 0 top
NOREF#1485  -  []  22.99 36.97 90 top
NOREF#1486  -  []  42.57 19.54 90 top
NOREF#1487  -  []  40.25 35.1 90 top
NOREF#1488  -  []  14.32 42.79 90 top
NOREF#1489  -  []  47.98 4.91 0 top
NOREF#1490  -  []  6.88 26.56 0 top
NOREF#1491  -  []  32.79 30.85 90 top
NOREF#1492  -  []  13.77 53.27 90 top
NOREF#1493  -  []  17.35 6.21 0 top
NOREF#1494  -  []  5.43 58.11 90 top
NOREF#1495  -  []  49.55 48.8 90 top
NOREF#1496  -  []  35.13 22.5 0 top
NOREF#1497  -  []  22.99 39.16 90 top
NOREF#1498  -  []  41.24 18.81 315 top
NOREF#1499  -  []  7.05 50.52 0 top
NOREF#1500  -  []  14.3 6.31 0 top
NOREF#1501  -  []  34.65 50.16 0 top
NOREF#1502  -  []  6.75 7.01 0 top
NOREF#1503  -  [unnamed#2]  2.52 58.98 0 top
NOREF#1504  -  []  28.86 18.44 90 top
NOREF#1505  -  []  20.22 6.3 90 top
NOREF#1506  -  []  29.11 13.64 90 top
NOREF#1507  -  []  13.69 39.45 0 top
NOREF#1508  -  []  42.56 59.28 90 top
NOREF#1509  -  []  34.54 15.42 90 top
NOREF#1510  -  []  35.43 21.9 90 top
NOREF#1511  -  []  32.04 32.67 90 top
NOREF#1512  -  []  38.57 9.45 90 top
NOREF#1513  -  []  31.83 11.45 0 top
NOREF#1514  -  []  43.36 48.14 0 top
NOREF#1515  -  []  33.64 43.47 90 top
NOREF#1516  -  []  28.89 62.5 90 top
NOREF#1517  -  []  10.6 32.45 0 top
NOREF#1518  -  []  46.92 4.06 90 top
NOREF#1519  -  []  23.12 14.83 0 top
NOREF#1520  -  []  14 19.28 0 top
NOREF#1521  -  []  41.75 31.4 90 top
NOREF#1522  -  []  35.2 20.53 0 top
NOREF#1523  -  []  22.85 29.25 90 top
NOREF#1524  -  []  44 32.65 90 top
NOREF#1525  -  []  34.8 11.89 0 top
NOREF#1526  -  []  28 36.95 90 top
NOREF#1527  -  []  8.67 14.25 90 top
NOREF#1528  -  []  44.31 23.64 90 top
NOREF#1529  -  []  16.89 14.12 0 top
NOREF#1530  -  []  31.79 13.45 0 top
NOREF#1531  -  []  33.1 50.19 0 top
NOREF#1532  -  []  28.8 52.13 90 top
NOREF#1533  -  []  48.6 57.02 90 top
NOREF#1534  -  []  24.17 39.68 90 top
NOREF#1535  -  []  43.66 43.36 90 top
NOREF#1536  -  []  31.59 32.42 90 top
NOREF#1537  -  []  40.22 9.92 0 top
NOREF#1538  -  []  43.23 16.92 90 top
NOREF#1539  -  []  10.62 13.59 90 top
NOREF#1540  -  []  39.39 14.53 0 top
NOREF#1541  -  []  43.23 17.43 90 top
NOREF#1542  -  []  13.31 13.51 90 top
NOREF#1543  -  []  25.74 34.03 0 top
NOREF#1544  -  []  15.4 39.02 0 top
NOREF#1545  -  []  12.43 49.79 0 top
NOREF#1546  -  []  12.12 43.48 0 top
NOREF#1547  -  []  11.75 30.88 90 top
NOREF#1548  -  []  46.12 21.66 90 top
NOREF#1549  -  []  9.3 31.04 90 top
NOREF#1550  -  []  6.83 29.98 90 top
NOREF#1551  -  []  22.69 38.14 0 top
NOREF#1552  -  []  45.32 15.6 0 top
NOREF#1553  -  []  34.24 35.43 0 top
NOREF#1554  -  []  28.45 36.78 0 top
NOREF#1555  -  []  38.78 20.07 0 top
NOREF#1556  -  []  45.52 29.34 0 top
NOREF#1557  -  []  25.31 36.13 90 top
NOREF#1558  -  []  14.2 39.12 0 top
NOREF#1559  -  []  44.1 10.71 90 top
NOREF#1560  -  []  37.94 42.74 90 top
NOREF#1561  -  []  39.4 11.09 0 top
NOREF#1562  -  []  27.3 13.7 0 top
NOREF#1563  -  []  7.6 45.57 90 top
NOREF#1564  -  []  17.14 45.18 90 top
NOREF#1565  -  []  52.6 59.64 90 top
NOREF#1566  -  []  43.94 42.96 90 top
NOREF#1567  -  []  30.12 20.23 0 top
NOREF#1568  -  []  32.79 8.95 0 top
NOREF#1569  -  []  7.6 49.73 90 top
NOREF#1570  -  []  18.61 50.09 0 top
NOREF#1571  -  []  43.27 58.95 90 top
NOREF#1572  -  []  33.12 50.37 90 top
NOREF#1573  -  []  13.72 40.58 90 top
NOREF#1574  -  []  20.62 13.55 0 top
NOREF#1575  -  []  45.91 34.82 90 top
NOREF#1576  -  []  21.67 39.25 0 top
NOREF#1577  -  []  30.46 36.59 0 top
NOREF#1578  -  []  42.84 58.24 0 top
NOREF#1579  -  []  16.74 22.61 90 top
NOREF#1580  -  []  14.49 6.25 90 top
NOREF#1581  -  []  47.18 11.75 90 top
NOREF#1582  -  []  22.72 24.8 0 top
NOREF#1583  -  []  34.74 56.24 90 top
NOREF#1584  -  []  40.47 61.23 90 top
NOREF#1585  -  []  42.26 4.91 0 top
NOREF#1586  -  []  31.11 35.97 0 top
NOREF#1587  -  []  42.62 5.84 0 top
NOREF#1588  -  []  23.75 13.56 90 top
NOREF#1589  -  []  37.3 11.53 90 top
NOREF#1590  -  []  37.12 50.25 90 top
NOREF#1591  -  []  27.81 32.29 0 top
NOREF#1592  -  []  25.47 31.96 0 top
NOREF#1593  -  []  15.62 6.52 90 top
NOREF#1594  -  []  16.46 24.05 0 top
NOREF#1595  -  []  27.46 31.21 0 top
NOREF#1596  -  []  31.65 30.77 0 top
NOREF#1597  -  []  44.31 64.37 90 top
NOREF#1598  -  []  43.46 43.05 0 top
NOREF#1599  -  []  39.83 38.62 90 top
NOREF#1600  -  []  37.84 16.12 0 top
NOREF#1601  -  []  45.89 4.84 90 top
NOREF#1602  -  []  22.31 16.96 0 top
NOREF#1603  -  []  14.13 31.45 0 top
NOREF#1604  -  []  42.56 58.98 0 top
NOREF#1605  -  []  35.57 28.68 90 top
NOREF#1606  -  []  45.46 27.46 0 top
NOREF#1607  -  []  37.07 9.39 90 top
NOREF#1608  -  []  14.61 52.88 0 top
NOREF#1609  -  []  31.27 51.66 0 top
NOREF#1610  -  []  29.14 62.37 90 top
NOREF#1611  -  []  13.48 39.45 90 top
NOREF#1612  -  []  27.42 30.67 0 top
NOREF#1613  -  []  34.42 61.21 0 top
NOREF#1614  -  []  28.25 12.65 0 top
NOREF#1615  -  []  48 57.02 0 top
NOREF#1616  -  []  31.73 15.5 90 top
NOREF#1617  -  []  25.68 14.93 0 top
NOREF#1618  -  [unnamed#2]  36.52 21.84 180 bottom
NOREF#1619  -  [unnamed#2]  45.34 65.79 180 bottom
NOREF#1620  -  [unnamed#2]  3.15 60.94 180 bottom
NOREF#1621  -  []  45.01 38.4 180 bottom
PMIC1  PM-4125-3-NSP194-TR-01-0  [BGA194_67X83_0D566_H10_QUALCOMM]  37.84 16.12 180 top
Q2707  MMDT3904-7-F_SOT363_6P  [SOT363_6P_22X21_H110]  44 31.9 180 bottom
Q2708  MMDT3904-7-F_SOT363_6P  [SOT363_6P_22X21_H110]  39.1 33.9 0 bottom
Q2709  MMDT3904-7-F_SOT363_6P  [SOT363_6P_22X21_H110]  40.9 29.9 180 bottom
Q2801  PJA3413_SOT23_3P  [SOT23_29X24_H110]  14.25 48.84 270 bottom
Q2802  MMBT3904W_SOT323_3P  [SOT323_21X20_H110]  16.51 46.18 270 bottom
QWIIC1  CI1104M1HR0-NH  [WTB4_60X51_1_H32_D90]  14.35 3.05 90 top
R501  0  [R0201_H030]  43.65 23.93 180 top
R502  0  [R0201_H030]  43.14 23.93 180 top
R503  0  [R0201_H030]  44.16 23.94 180 top
R601  47K  [R0201_H030]  40.34 12.1 90 top
R603  0  [R0201_H030]  46.04 16.4 270 top
R604  0  [R0201_H030]  46.04 16.91 270 top
R605  7.5K_1%  [R0201_H030]  38.93 9.74 0 top
R606  100K  [R0201_H030]  38.42 9.75 0 top
R607  56K  [R0201_H030]  44.07 16.01 270 top
R701  22  [R0201_H030]  30.04 13.05 90 top
R702  0  [R0201_H030]  30.05 13.56 90 top
R703  0  [R0201_H030]  30.04 12.5 90 top
R705  0  [R0201_H030]  36.92 9.7 0 top
R706  0  [R0201_H030]  35.63 9.96 270 top
R707  5.1K  [R0201_H030]  36.4 10.74 0 top
R708  0  [R0201_H030]  38.86 43.05 180 top
R709  0  [R0201_H030]  35.56 8.67 270 top
R901  0  [R0201_H030]  34.77 22.2 180 top
R902  0  [R0201_H030]  35.28 22.2 180 top
R1101  10K_1%  [R0201_H030]  16.07 36.4 270 bottom
R1102  10K_1%  [R0201_H030]  19.78 32.32 90 bottom
R1201  0  [R0201_H030]  23 25.16 180 top
R1202  100_1%  [R0201_H030]  31.84 26.42 0 top
R1203  4.02K_1%  [R0201_H030]  31.33 26.42 0 top
R1204  0  [R0201_H030]  6.36 49.18 90 top
R1205  0  [R0201_H030]  21.99 23.52 180 top
R1206  0  [R0201_H030]  22.47 21.09 180 top
R1207  22  [R0201_H030]  35.6 26.55 90 top
R1208  1K  [R0201_H030]  26.66 26.85 90 top
R1301  0  [R0201_H030]  23.51 25.16 0 top
R1302  0  [R0201_H030]  23.85 26.31 0 top
R1303  2.2K  [R0201_H030]  21.82 37.27 90 top
R1304  0  [R0201_H030]  22.84 37.27 90 top
R1305  2.2K  [R0201_H030]  21.82 38.41 90 top
R1306  0  [R0201_H030]  22.84 38.41 90 top
R1307  2.2K  [R0201_H030]  21.82 37.84 90 top
R1308  0  [R0201_H030]  22.84 37.84 90 top
R1309  2.2K  [R0201_H030]  21.82 38.95 90 top
R1310  0  [R0201_H030]  22.84 38.95 90 top
R1311  2.2K  [R0201_H030]  27.74 18.72 180 top
R1312  0  [R0201_H030]  28.28 19.58 90 top
R1313  2.2K  [R0201_H030]  22.46 16.1 270 top
R1314  0  [R0201_H030]  22.46 16.66 90 top
R1315  10K_1%  [R0201_H030]  21.82 39.46 90 top
R1316  10K_1%  [R0201_H030]  22.84 39.46 90 top
R1317  10K_1%  [R0201_H030]  21.82 40.02 90 top
R1318  10K_1%  [R0201_H030]  22.84 40.02 90 top
R1319  10K_1%  [R0201_H030]  25.15 15.9 180 top
R1320  10K_1%  [R0201_H030]  24.58 15.9 0 top
R1321  0  [R0201_H030]  38.31 43.04 0 top
R1401  240_1%  [R0201_H030]  34.39 35.13 180 bottom
R1501  0  [R0201_H030]  38.99 50.37 90 top
R1502  0  [R0201_H030]  38.99 50.91 90 top
R1503  0  [R0201_H030]  38.96 51.69 90 top
R1504  0  [R0201_H030]  38.96 52.22 90 top
R1505  0  [R0201_H030]  36.91 49.43 0 top
R1506  0  [R0201_H030]  37.44 49.43 0 top
R1507  0  [R0201_H030]  38.96 52.93 90 top
R1508  0  [R0201_H030]  38.96 53.44 90 top
R1509  0  [R0201_H030]  35.71 49.43 0 top
R1510  0  [R0201_H030]  36.22 49.43 0 top
R1522  1.4K_1%  [R0201_H030]  30.79 26.42 0 top
R1601  3.01K_1%  [R0201_H030]  29.41 26.42 0 top
R1602  6.04K_1%  [R0201_H030]  35.37 41.22 270 top
R2113  10K_1%  [R0201_H030]  34.1 24.5 180 bottom
R2114  10K_1%  [R0201_H030]  34.1 25.55 180 bottom
R2201  240_1%  [R0201_H030]  40.9 41.11 90 bottom
R2202  240_1%  [R0201_H030]  42.81 41.95 270 bottom
R2501  0  [R0201_H030]  6.62 25.08 0 bottom
R2502  0  [R0201_H030]  7.03 27.36 0 bottom
R2503  0  [R0201_H030]  6.83 24.3 90 bottom
R2504  0  [R0201_H030]  7.03 26.26 0 bottom
R2505  0  [R0201_H030]  16.38 24.66 270 bottom
R2506  0  [R0201_H030]  17.78 24.92 270 bottom
R2507  0  [R0201_H030]  16.59 22.91 90 bottom
R2508  0  [R0201_H030]  7.47 20.31 90 bottom
R2509  0  [R0201_H030]  10.59 20.07 180 bottom
R2511  0  [R0201_H030]  10.06 20.07 180 bottom
R2512  1M  [R0201_H030]  13.79 18.54 270 bottom
R2513  0  [R0201_H030]  13.49 19.91 180 bottom
R2514  0  [R0201_H030]  14.07 19.91 0 bottom
R2515  100K  [R0201_H030]  46.3 45.17 0 bottom
R2516  0  [R0201_H030]  6.52 26.58 0 bottom
R2517  0  [R0201_H030]  7.57 30.36 270 bottom
R2605  1K  [R0201_H030]  14.76 52.58 180 bottom
R2606  1K  [R0201_H030]  15.7 52.8 180 bottom
R2607  0  [R0201_H030]  14.8 53.4 90 bottom
R2608  0  [R0201_H030]  13.99 52.84 90 bottom
R2609  1K  [R0201_H030]  30.52 62.74 90 bottom
R2610  1K  [R0201_H030]  29.68 61.75 180 bottom
R2611  0  [R0201_H030]  30.45 62 270 bottom
R2612  0  [R0201_H030]  31.32 62.25 180 bottom
R2613  2.2K  [R0201_H030]  14.34 6.83 180 top
R2614  2.2K  [R0201_H030]  16.01 6.81 180 top
R2615  0  [R0201_H030]  15.47 6.82 0 top
R2616  0  [R0201_H030]  14.86 6.83 0 top
R2617  0  [R0201_H030]  21.43 4.22 90 top
R2618  0  [R0201_H030]  21.4 3.61 90 top
R2619  0  [R0201_H030]  21.38 2.98 90 top
R2621  100K  [R0201_H030]  6.23 43.59 0 bottom
R2622  2.2K  [R0201_H030]  6.9 36.19 90 bottom
R2623  0  [R0201_H030]  17.58 22.48 270 bottom
R2624  0  [R0201_H030]  7.01 19.48 180 bottom
R2625  0  [R0201_H030]  7.8 19.51 180 bottom
R2626  0  [R0201_H030]  7.11 28.75 90 bottom
R2631  0  [R0201_H030]  25.83 14.63 0 bottom
R2632  0  [R0201_H030]  25.02 14.63 0 bottom
R2633  0  [R0201_H030]  21.68 14.02 0 bottom
R2634  0  [R0201_H030]  23.27 14.53 0 bottom
R2635  0  [R0201_H030]  22.73 14.53 0 bottom
R2636  0  [R0201_H030]  22.33 4.37 270 bottom
R2637  0  [R0201_H030]  21.27 4.37 90 bottom
R2638  0  [R0201_H030]  28.18 63.4 270 bottom
R2639  0  [R0201_H030]  28.18 62.89 270 bottom
R2640  0  [R0201_H030]  8.99 29.24 0 bottom
R2641  0  [R0201_H030]  8.46 29.24 0 bottom
R2642  2.2K  [R0201_H030]  45.47 47.22 180 bottom
R2643  2.2K  [R0201_H030]  45.47 46.15 0 bottom
R2644  0  [R0201_H030]  46.38 46.41 270 bottom
